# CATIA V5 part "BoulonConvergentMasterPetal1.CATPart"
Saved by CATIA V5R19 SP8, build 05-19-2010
Part number: BoulonConvergentMasterPetal1
Bounding box of the stored display mesh (mm): x -28 to 24, y 722 to 738, z 392 to 408
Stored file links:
  G:\EU_thinkMotion\CFAO_2010\MMS_groupe3\MMS_groupe3\A reprendre\fovide\fovide\BoulonConvergentMasterPetal1.CATPart
  C:\Users\Rodger\Desktop\Part11.CATPart
  G:\EU_thinkMotion\CFAO_2010\MMS_groupe3\MMS_groupe3\A reprendre\fovide\fovide\fovide.CATProduct
  G:\EU_thinkMotion\CFAO_2010\MMS_groupe3\MMS_groupe3\A reprendre\fovide\fovide\Convergent Master Petal 4.CATPart
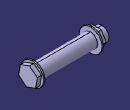
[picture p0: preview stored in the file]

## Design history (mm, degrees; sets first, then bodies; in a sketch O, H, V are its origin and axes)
Parameters
  Diametre = 10 mm
  Longueur = 40 mm
Set1
  DatumSurface1: linked copy from another document
  Point1: linked copy from another document
Body1 (main body)
Body2
  Sketch1 on DatumSurface1, origin (20, 0, 20), H (0, 0, -1), V (0, 1, 0)
    circle A1 centre (-380, 730) radius 8
    point P1 (-380, 730)
    reference projected point E1 (-380, 730) from Point1
    radius A1 = 8 {= Diametre *8/10}
    coincidence: P1 E1
  Pad1: profile Sketch1, direction (1, 0, 0), length 1
  Sketch2 on end face of Pad1, origin (21, 0, 22), H (0, 0, -1), V (0, 1, 0)
    point P1 (-378, 730)
    point P2 (-375.5061, 723.4593)
    point P3 (-371.0887, 728.8894)
    point P4 (-373.5825, 735.4301)
    point P5 (-380.4939, 736.5407)
    point P6 (-384.9113, 731.1106)
    point P7 (-382.4175, 724.5699)
    point P8 (-373.2974, 726.1744)
    line L1 (-375.5061, 723.4593) -> (-371.0887, 728.8894)
    line L2 (-371.0887, 728.8894) -> (-373.5825, 735.4301)
    line L3 (-373.5825, 735.4301) -> (-380.4939, 736.5407)
    line L4 (-380.4939, 736.5407) -> (-384.9113, 731.1106)
    line L5 (-384.9113, 731.1106) -> (-382.4175, 724.5699)
    line L6 (-382.4175, 724.5699) -> (-375.5061, 723.4593)
    construction line L7 (-378, 730) -> (-373.2974, 726.1744)
    construction circle A1 centre (-378, 730) radius 7
    construction arc A2 centre (-384.9113, 731.1106) radius 7 from (-380.4939, 736.5407) to (-382.4175, 724.5699) cw
    construction arc A3 centre (-371.0887, 728.8894) radius 7 from (-373.5825, 735.4301) to (-375.5061, 723.4593) ccw
    reference projected point E1 (-378, 730) from Point1
    radius A1 = 7 {= Diametre *7/10}
    coincidence: A1 P2, A1 P3, A1 P4, A1 P5, A1 P6, A1 P7, A2 P1, A3 P1, P1 E1
    midpoint: P8 L1
    parallelism: L1 L4
  Pad2: profile Sketch2, direction (1, 0, 0), length 3
  Sketch3 on start face of Pad1, origin (20, 0, 20), H (0, 0, -1), V (0, -1, 0)
    circle A1 centre (-380, -730) radius 5
    point P1 (-380, -730)
    reference projected point E1 (-380, -730) from Point1
    radius A1 = 5 {= Diametre /2}
    coincidence: P1 E1
  Pad3: profile Sketch3, direction (-1, 0, 0), length 40 {= Longueur}
  Sketch4 on end face of Pad3, origin (-20, 0, -60), H (0, 0, -1), V (0, -1, 0)
    circle A1 centre (-460, -730) radius 8
    point P1 (-460, -730)
    reference projected point E1 (-460, -730) from Point1
    radius A1 = 8 {= Diametre *8/10}
    coincidence: P1 E1
  Pad4: profile Sketch4, direction (-1, 0, 0), length 1
  Sketch5 on end face of Pad4, origin (-21, 0, -62), H (0, 0, -1), V (0, -1, 0)
    point P1 (-462, -730)
    point P2 (-462.0478, -736.9998)
    point P3 (-455.9619, -733.5413)
    point P4 (-455.9141, -726.5415)
    point P5 (-461.9522, -723.0002)
    point P6 (-468.0381, -726.4587)
    point P7 (-468.0859, -733.4585)
    point P8 (-459.0048, -735.2706)
    line L1 (-462.0478, -736.9998) -> (-455.9619, -733.5413)
    line L2 (-455.9619, -733.5413) -> (-455.9141, -726.5415)
    line L3 (-455.9141, -726.5415) -> (-461.9522, -723.0002)
    line L4 (-461.9522, -723.0002) -> (-468.0381, -726.4587)
    line L5 (-468.0381, -726.4587) -> (-468.0859, -733.4585)
    line L6 (-468.0859, -733.4585) -> (-462.0478, -736.9998)
    construction line L7 (-462, -730) -> (-459.0048, -735.2706)
    construction circle A1 centre (-462, -730) radius 7
    construction arc A2 centre (-468.0381, -726.4587) radius 7 from (-461.9522, -723.0002) to (-468.0859, -733.4585) cw
    construction arc A3 centre (-455.9619, -733.5413) radius 7 from (-455.9141, -726.5415) to (-462.0478, -736.9998) ccw
    reference projected point E1 (-462, -730) from Point1
    radius A1 = 7 {= Diametre *7/10}
    coincidence: A1 P2, A1 P3, A1 P4, A1 P5, A1 P6, A1 P7, A2 P1, A3 P1, P1 E1
    midpoint: P8 L1
    parallelism: L1 L4
  Pad5: profile Sketch5, direction (-1, 0, 0), length 3
  Sketch6 on end face of Pad5, origin (-24, 0, -68), H (0, 0, -1), V (0, -1, 0)
    circle A1 centre (-468, -730) radius 5
    point P1 (-468, -730)
    reference projected point E1 (-468, -730) from Point1
    radius A1 = 5 {= Diametre /2}
    coincidence: P1 E1
  Pad6: profile Sketch6, direction (-1, 0, 0), length 4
